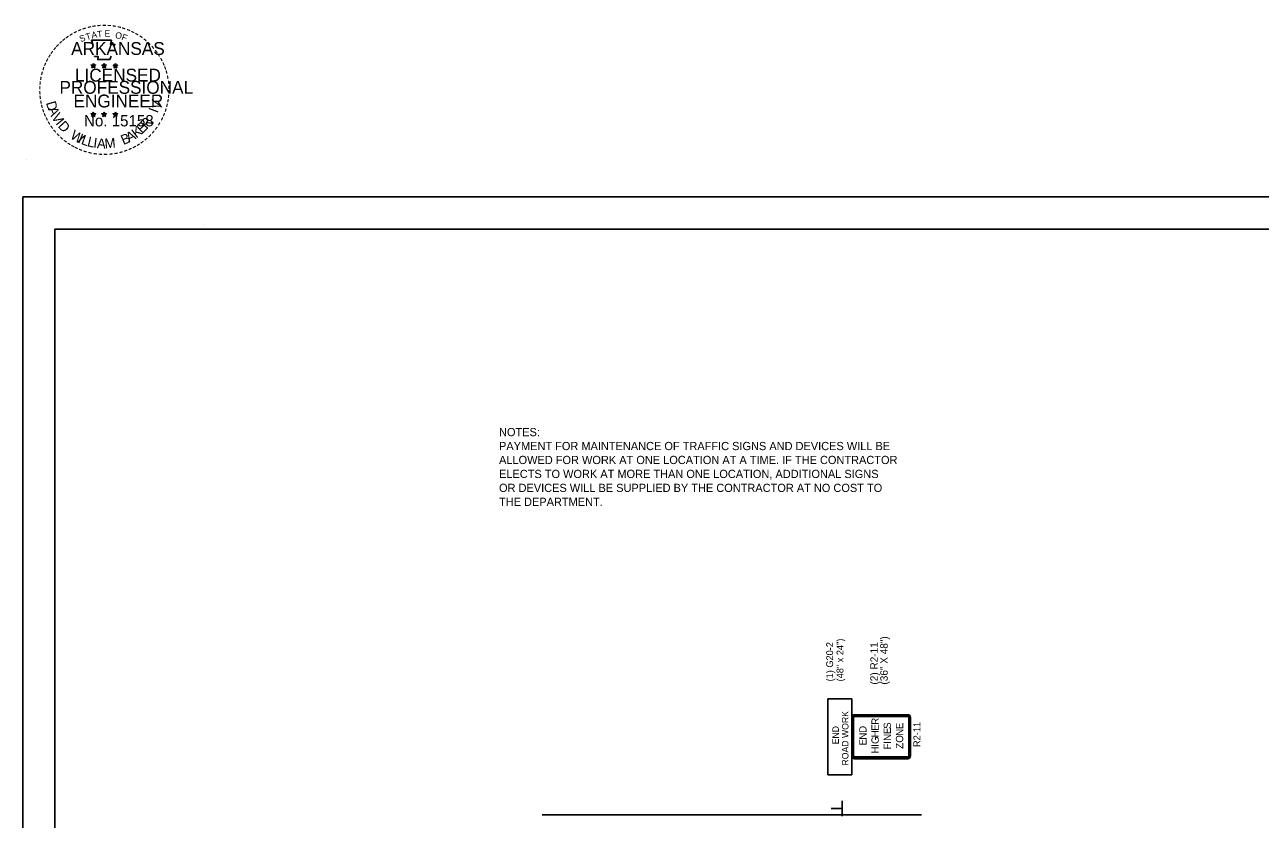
# Model space of a CAD drawing. Extents: x 32485 to 39285, y 55121 to 58033.
# Drawn here: x 35886 to 36848, y 57379 to 57998 of the extents above; entities that cross this region are included whole.
import ezdxf

# ---------------------------------------------------------------- set-up
doc = ezdxf.new("R2010")
doc.units = 0
for name, color, linetype in [('Default', 7, 'Continuous'), ('R_Border', 7, 'Continuous'), ('R_Border Notes', 7, 'Continuous'), ('R_Dimension', 7, 'Continuous'), ('R_Draft', 7, 'Continuous'), ('R_Exist Surface', 7, 'Continuous'), ('SHET_Stamp-PE-Chief-Eng', 7, 'Continuous')]:
    doc.layers.add(name, color=color, linetype=linetype)

msp = doc.modelspace()

# ---------------------------------------------------------------- linework, layer by layer
at = {"layer": 'Default'}
for p, q in [((36530.23, 57458.5), (36530.23, 57428.52)), ((36530.82, 57458.5), (36530.82, 57428.52)), ((36531.65, 57428.52), (36531.65, 57458.5)), ((36573.77, 57460.65), (36532.37, 57460.65)), ((36573.77, 57460.05), (36532.37, 57460.05)), ((36532.37, 57459.22), (36573.77, 57459.22)), ((36574.48, 57458.5), (36574.48, 57428.52)), ((36575.32, 57428.52), (36575.32, 57458.5)), ((36575.91, 57428.52), (36575.91, 57458.5)), ((36573.77, 57427.81), (36532.37, 57427.81)), ((36532.37, 57426.98), (36573.77, 57426.98)), ((36532.37, 57426.38), (36573.77, 57426.38))]:
    msp.add_line(p, q, dxfattribs=at)
msp.add_lwpolyline([(35885, 57863.91), (35885, 56763.91), (37585, 56763.91), (37585, 57863.91)], close=True, dxfattribs=at)
for centre, radius, start, end in [((36532.37, 57458.5), 2.14, 90, 180), ((36532.37, 57458.5), 1.55, 90, 180), ((36532.37, 57458.5), 0.714, 90, 180), ((36573.77, 57458.5), 2.14, 0.00001, 90.00001), ((36573.77, 57458.5), 1.55, 0, 90.00001), ((36573.77, 57458.5), 0.714, 0, 90.00001), ((36532.37, 57428.52), 2.14, 180, 270), ((36532.37, 57428.52), 1.55, 180, 270.00001), ((36532.37, 57428.52), 0.714, 180, 270.00001), ((36573.77, 57428.52), 2.14, 270, 0.00001), ((36573.77, 57428.52), 1.55, 270.00001, 0), ((36573.77, 57428.52), 0.714, 270.00001, 0)]:
    msp.add_arc(centre, radius, start, end, dxfattribs=at)
at = {"layer": 'R_Border'}
for p, q in [((36511.61, 57473.14), (36511.61, 57413.89)), ((36530.23, 57473.14), (36511.61, 57473.14)), ((36530.23, 57473.14), (36530.23, 57413.89)), ((36530.23, 57413.89), (36511.61, 57413.89)), ((36522.44, 57387.6), (36514.22, 57387.56)), ((36522.59, 57393.59), (36522.64, 57381.54))]:
    msp.add_line(p, q, dxfattribs=at)
at = {"layer": 'R_Border Notes'}
msp.add_line((36026.11, 57842.49), (36026.11, 57842.49), dxfattribs=at)
msp.add_line((36026.11, 57842.49), (36026.11, 57842.49), dxfattribs=at)
for points in [[(35885, 56763.91), (37585, 56763.91), (37585, 57863.91), (35885, 57863.91)], [(35910, 56788.91), (37560, 56788.91), (37560, 57838.91), (35910, 57838.91)]]:
    msp.add_lwpolyline(points, close=True, dxfattribs=at)
at = {"layer": 'R_Dimension'}
for p, q in [((35938.12, 57966.59), (35939.86, 57966.03)), ((35938.12, 57966.59), (35939.38, 57966.36)), ((35938.12, 57966.59), (35939.3, 57965.98)), ((35938.78, 57964.55), (35939.86, 57966.03)), ((35938.78, 57964.55), (35939.41, 57965.77)), ((35938.78, 57964.55), (35939.85, 57965.63)), ((35939.86, 57967.86), (35939.66, 57966.6)), ((35940.93, 57964.55), (35939.85, 57965.62)), ((35939.86, 57966.03), (35939.86, 57967.86)), ((35939.86, 57967.86), (35940.11, 57966.61)), ((35941.6, 57966.59), (35939.86, 57966.03)), ((35940.93, 57964.55), (35939.86, 57966.03)), ((35941.6, 57966.59), (35940.17, 57966.34)), ((35940.93, 57964.55), (35940.24, 57966)), ((35941.6, 57966.59), (35940.58, 57966.08)), ((35946.47, 57966.59), (35948.21, 57966.03)), ((35946.47, 57966.59), (35947.73, 57966.36)), ((35946.47, 57966.59), (35947.65, 57965.98)), ((35947.13, 57964.55), (35948.21, 57966.03)), ((35947.13, 57964.55), (35947.76, 57965.77)), ((35947.13, 57964.55), (35948.2, 57965.63)), ((35948.21, 57967.86), (35948.01, 57966.6)), ((35949.28, 57964.55), (35948.2, 57965.62)), ((35948.21, 57966.03), (35948.21, 57967.86)), ((35948.21, 57967.86), (35948.46, 57966.61)), ((35949.95, 57966.59), (35948.21, 57966.03)), ((35949.28, 57964.55), (35948.21, 57966.03)), ((35949.95, 57966.59), (35948.52, 57966.34)), ((35949.28, 57964.55), (35948.59, 57966)), ((35949.95, 57966.59), (35948.93, 57966.08)), ((35955.29, 57966.53), (35957.03, 57965.97)), ((35955.29, 57966.53), (35956.55, 57966.3)), ((35955.29, 57966.53), (35956.47, 57965.92)), ((35955.95, 57964.49), (35957.03, 57965.97)), ((35955.95, 57964.49), (35956.58, 57965.71)), ((35955.95, 57964.49), (35957.02, 57965.57)), ((35957.03, 57967.8), (35956.83, 57966.54)), ((35958.1, 57964.49), (35957.02, 57965.56)), ((35957.03, 57965.97), (35957.03, 57967.8)), ((35957.03, 57967.8), (35957.28, 57966.55)), ((35958.77, 57966.53), (35957.03, 57965.97)), ((35958.1, 57964.49), (35957.03, 57965.97)), ((35958.77, 57966.53), (35957.34, 57966.28)), ((35958.1, 57964.49), (35957.41, 57965.94)), ((35958.77, 57966.53), (35957.75, 57966.02)), ((35938.1, 57928.72), (35939.84, 57928.17)), ((35938.1, 57928.72), (35939.36, 57928.5)), ((35938.1, 57928.72), (35939.28, 57928.11)), ((35938.76, 57926.68), (35939.84, 57928.17)), ((35938.76, 57926.68), (35939.39, 57927.9)), ((35938.76, 57926.68), (35939.83, 57927.77)), ((35939.84, 57929.99), (35939.64, 57928.73)), ((35940.91, 57926.68), (35939.83, 57927.75)), ((35939.84, 57928.17), (35939.84, 57929.99)), ((35939.84, 57929.99), (35940.09, 57928.74)), ((35941.58, 57928.72), (35939.84, 57928.17)), ((35940.91, 57926.68), (35939.84, 57928.17)), ((35941.58, 57928.72), (35940.15, 57928.48)), ((35940.91, 57926.68), (35940.22, 57928.14)), ((35941.58, 57928.72), (35940.56, 57928.21)), ((35946.44, 57928.72), (35948.19, 57928.17)), ((35946.44, 57928.72), (35947.71, 57928.5)), ((35946.44, 57928.72), (35947.63, 57928.11)), ((35947.11, 57926.68), (35948.19, 57928.17)), ((35947.11, 57926.68), (35947.74, 57927.9)), ((35947.11, 57926.68), (35948.18, 57927.77)), ((35948.19, 57929.99), (35947.98, 57928.73)), ((35949.25, 57926.68), (35948.18, 57927.75)), ((35948.19, 57928.17), (35948.19, 57929.99)), ((35948.19, 57929.99), (35948.43, 57928.74)), ((35949.92, 57928.72), (35948.19, 57928.17)), ((35949.25, 57926.68), (35948.19, 57928.17)), ((35949.92, 57928.72), (35948.49, 57928.48)), ((35949.25, 57926.68), (35948.57, 57928.14)), ((35949.92, 57928.72), (35948.9, 57928.21)), ((35955.28, 57928.67), (35957.02, 57928.12)), ((35955.28, 57928.67), (35956.54, 57928.45)), ((35955.28, 57928.67), (35956.46, 57928.06)), ((35955.94, 57926.63), (35957.02, 57928.12)), ((35955.94, 57926.63), (35956.57, 57927.85)), ((35955.94, 57926.63), (35957.01, 57927.72)), ((35957.02, 57929.94), (35956.82, 57928.68)), ((35958.09, 57926.63), (35957.01, 57927.7)), ((35957.02, 57928.12), (35957.02, 57929.94)), ((35957.02, 57929.94), (35957.27, 57928.69)), ((35958.76, 57928.67), (35957.02, 57928.12)), ((35958.09, 57926.63), (35957.02, 57928.12)), ((35958.76, 57928.67), (35957.33, 57928.43)), ((35958.09, 57926.63), (35957.4, 57928.09)), ((35958.76, 57928.67), (35957.74, 57928.16))]:
    msp.add_line(p, q, dxfattribs=at)
for points in [[(35938.32, 57985.98), (35939.67, 57981.84)], [(35955.88, 57981.37), (35956.59, 57982.79), (35953.16, 57982.67), (35953.9, 57985.98), (35938.32, 57985.98)], [(35940.78, 57973.86), (35940.78, 57973.43), (35943.6, 57973.33), (35943.33, 57970.97), (35952.68, 57970.97), (35953.68, 57973.65)], [(35939.86, 57967.86), (35940.93, 57964.55), (35938.12, 57966.59), (35941.6, 57966.59), (35938.78, 57964.55), (35939.86, 57967.86)], [(35948.21, 57967.86), (35949.28, 57964.55), (35946.47, 57966.59), (35949.95, 57966.59), (35947.13, 57964.55), (35948.21, 57967.86)], [(35957.03, 57967.8), (35958.1, 57964.49), (35955.29, 57966.53), (35958.77, 57966.53), (35955.95, 57964.49), (35957.03, 57967.8)], [(35939.84, 57929.99), (35940.91, 57926.68), (35938.1, 57928.72), (35941.58, 57928.72), (35938.76, 57926.68), (35939.84, 57929.99)], [(35948.19, 57929.99), (35949.25, 57926.68), (35946.44, 57928.72), (35949.92, 57928.72), (35947.11, 57926.68), (35948.19, 57929.99)], [(35957.02, 57929.94), (35958.09, 57926.63), (35955.28, 57928.67), (35958.76, 57928.67), (35955.94, 57926.63), (35957.02, 57929.94)]]:
    msp.add_lwpolyline(points, dxfattribs=at)
for centre, radius in [((35939.86, 57966.03), 0.861), ((35939.86, 57966.03), 0.723), ((35939.86, 57966.03), 0.579), ((35939.86, 57966.03), 0.495), ((35939.86, 57966.03), 0.374), ((35939.86, 57966.03), 0.248), ((35939.86, 57966.03), 0.148), ((35948.21, 57966.03), 0.861), ((35948.21, 57966.03), 0.723), ((35948.21, 57966.03), 0.579), ((35948.21, 57966.03), 0.495), ((35948.21, 57966.03), 0.374), ((35948.21, 57966.03), 0.248), ((35948.21, 57966.03), 0.148), ((35957.03, 57965.97), 0.861), ((35957.03, 57965.97), 0.723), ((35957.03, 57965.97), 0.579), ((35957.03, 57965.97), 0.495), ((35957.03, 57965.97), 0.374), ((35957.03, 57965.97), 0.248), ((35957.03, 57965.97), 0.148), ((35939.84, 57928.16), 0.861), ((35939.84, 57928.16), 0.723), ((35939.84, 57928.16), 0.579), ((35939.84, 57928.16), 0.495), ((35939.84, 57928.16), 0.374), ((35939.84, 57928.16), 0.248), ((35939.84, 57928.16), 0.148), ((35948.18, 57928.16), 0.861), ((35948.18, 57928.16), 0.723), ((35948.18, 57928.16), 0.579), ((35948.18, 57928.16), 0.495), ((35948.18, 57928.16), 0.374), ((35948.18, 57928.16), 0.248), ((35948.18, 57928.16), 0.148), ((35957.02, 57928.11), 0.861), ((35957.02, 57928.11), 0.723), ((35957.02, 57928.11), 0.579), ((35957.02, 57928.11), 0.495), ((35957.02, 57928.11), 0.374), ((35957.02, 57928.11), 0.248), ((35957.02, 57928.11), 0.148)]:
    msp.add_circle(centre, radius, dxfattribs=at)
at = {"layer": 'R_Exist Surface'}
msp.add_line((36289.08, 57382.7), (36584.44, 57382.7), dxfattribs=at)
at = {"layer": 'SHET_Stamp-PE-Chief-Eng'}
msp.add_line((35887.86, 57893.03), (35887.86, 57893.03), dxfattribs=at)

# ---------------------------------------------------------------- texts
at = {"layer": 'Default'}
for s, height, p in [('NOTES: ', 6.392, (36255.62, 57677.6)), ('PAYMENT FOR MAINTENANCE OF TRAFFIC SIGNS AND DEVICES WILL BE ', 6.3923, (36255.62, 57666.73)), ('ALLOWED FOR WORK AT ONE LOCATION AT A TIME. IF THE CONTRACTOR', 6.3923, (36255.62, 57655.87)), ('ELECTS TO WORK AT MORE THAN ONE LOCATION, ADDITIONAL SIGNS', 6.3923, (36255.62, 57645)), ('OR DEVICES WILL BE SUPPLIED BY THE CONTRACTOR AT NO COST TO ', 6.3923, (36255.62, 57634.13)), ('THE DEPARTMENT.', 6.3923, (36255.62, 57623.27))]:
    msp.add_text(s, height=height, dxfattribs=at).set_placement(p)
for s, height, p in [('R', 5.71, (36551.17, 57452.75)), ('E', 5.71, (36551.17, 57448.23)), ('S', 5.71, (36560.68, 57449.6)), ('E', 5.71, (36570.2, 57449.4)), ('R2-11', 5.384, (36583.53, 57435.46)), ('D', 5.71, (36541.65, 57446.46)), ('N', 5.71, (36541.65, 57441.2)), ('G', 5.71, (36551.17, 57437.83)), ('H', 5.71, (36551.17, 57442.97)), ('E', 5.71, (36560.68, 57445.49)), ('N', 5.71, (36560.68, 57440.23)), ('O', 5.71, (36570.2, 57438.83)), ('N', 5.71, (36570.2, 57444.14)), ('E', 5.71, (36541.65, 57436.68)), ('I', 5.71, (36551.17, 57435.66)), ('H', 5.71, (36551.17, 57430.4)), ('I', 5.71, (36560.68, 57437.94)), ('F', 5.71, (36560.68, 57433.54)), ('Z', 5.71, (36570.2, 57434.08))]:
    msp.add_text(s, height=height, rotation=90, dxfattribs=at).set_placement(p)
at = {"layer": 'R_Border'}
for s, height, p in [('(1) G20-2', 5.353, (36515.65, 57486.59)), ('(48" x 24")', 5.3523, (36523.68, 57486.59)), ('ROAD WORK', 5.058, (36527.6, 57421.06)), ('END', 5.058, (36520.13, 57437.57))]:
    msp.add_text(s, height=height, rotation=90, dxfattribs=at).set_placement(p)
at = {"layer": 'R_Dimension'}
for s, height, rotation, p in [('-', 8, 34.06357, (35922.74, 57986.83)), ('-', 8, 28.79182, (35925.73, 57988.68)), ('-', 8, 24.30721, (35928.89, 57990.27)), ('-', 8, 19.17608, (35932.06, 57991.61)), ('T', 5, 16.4036, (35934.67, 57986.02)), ('-', 8, 13.63015, (35935.81, 57992.82)), ('A', 5, 11.21318, (35938.8, 57987.28)), ('-', 8, 10.21935, (35939.2, 57993.63)), ('T', 5, 6.02276, (35943.04, 57988.11)), ('-', 8, 5.89682, (35942.85, 57994.18)), ('-', 8, 0.18623, (35946.71, 57994.54)), ('E', 5, 0.83234, (35948.57, 57988.66)), ('-', 8, 357.74304, (35950.32, 57994.47)), ('-', 8, 352.16172, (35954.04, 57994.19)), ('O', 5, 350.4515, (35956.59, 57987.61)), ('-', 8, 347.20489, (35957.64, 57993.62)), ('-', 8, 342.3362, (35960.81, 57992.85)), ('-', 8, 337.85509, (35964.49, 57991.73)), ('-', 8, 334.12109, (35967.64, 57990.38)), ('-', 8, 329.64089, (35970.54, 57988.96)), ('-', 8, 48.42305, (35913.07, 57978.49)), ('-', 8, 42.96224, (35915.31, 57980.88)), ('-', 8, 38.95066, (35917.47, 57982.97)), ('-', 8, 36.23174, (35919.85, 57984.86)), ('S', 5, 21.59401, (35930.1, 57984.37)), ('F', 5, 340.07066, (35961.36, 57986.47)), ('-', 8, 325.86266, (35973.75, 57987.16)), ('-', 8, 320.52971, (35976.8, 57985.03)), ('-', 8, 315.57859, (35979.8, 57982.59)), ('-', 8, 309.87973, (35982.64, 57979.84)), ('-', 8, 58.07063, (35907.36, 57970.59)), ('-', 8, 54.23247, (35908.99, 57973.23)), ('-', 8, 50.61418, (35911.05, 57976.06)), ('-', 8, 306.65218, (35985.27, 57976.83)), ('-', 7, 303.67529, (35987.7, 57973.99)), ('-', 8, 299.66835, (35989.29, 57970.95)), ('-', 8, 72.39447, (35903.41, 57961.32)), ('-', 8, 67.77427, (35904.5, 57964.47)), ('-', 8, 62.87135, (35905.8, 57967.52)), ('-', 8, 294.66279, (35990.91, 57967.89)), ('-', 8, 290.57283, (35992.2, 57965.01)), ('-', 8, 285.12326, (35993.37, 57962.11)), ('-', 8, 85.18634, (35901.38, 57950.73)), ('-', 8, 81.20126, (35901.76, 57954.18)), ('-', 8, 75.46096, (35902.42, 57957.75)), ('-', 8, 280.54934, (35994.37, 57958.4)), ('-', 8, 276.59616, (35995.18, 57954.56)), ('-', 8, 94.19588, (35901.43, 57943.6)), ('-', 8, 89.06224, (35901.26, 57947.22)), ('-', 8, 263.5172, (35995.55, 57944.46)), ('-', 8, 274.33011, (35995.48, 57950.95)), ('-', 8, 269.94067, (35995.65, 57947.79)), ('-', 8, 98.94793, (35901.79, 57940.26)), ('-', 8, 101.71495, (35902.47, 57936.6)), ('-', 8, 105.45785, (35903.28, 57933.62)), ('D', 7.7, 286.28478, (35902.91, 57937.29)), ('V', 7.7, 72.65729, (35990.87, 57931.48)), ('-', 8, 255.7626, (35994.65, 57937.8)), ('-', 8, 260.99529, (35995.2, 57941.19)), ('-', 8, 109.08742, (35904.35, 57930.47)), ('-', 8, 114.06432, (35905.62, 57927.49)), ('-', 8, 115.72885, (35907.15, 57924.4)), ('A', 7.7, 292.78351, (35904.37, 57932.28)), ('V', 7.7, 300.79357, (35906.94, 57926.38)), ('I', 7.7, 308.35023, (35910.1, 57921.2)), ('R', 7.7, 50.36514, (35981.51, 57916.34)), ('I', 7.7, 69.03009, (35989.76, 57928.79)), ('-', 8, 244.61971, (35991.32, 57927.69)), ('-', 8, 247.88866, (35992.63, 57930.83)), ('-', 8, 252.86809, (35993.74, 57934.2)), ('-', 8, 120.44712, (35908.93, 57921.47)), ('-', 8, 125.89344, (35910.95, 57918.66)), ('-', 8, 130.71812, (35913.26, 57915.9)), ('D', 7.7, 311.97742, (35911.85, 57918.87)), ('W', 7.7, 328.07311, (35921.24, 57910.04)), ('A', 7.7, 28.90423, (35967.7, 57906.17)), ('K', 7.7, 36.91429, (35973.29, 57909.35)), ('E', 7.7, 44.01755, (35977.84, 57912.8)), (',', 7.7, 57.4684, (35985.12, 57920.76)), ('-', 8, 231.25377, (35985.19, 57917.83)), ('-', 8, 233.84524, (35987.34, 57920.66)), ('-', 8, 239.07125, (35989.35, 57923.93)), ('-', 8, 134.22381, (35915.84, 57913.18)), ('-', 8, 138.93382, (35918.47, 57910.86)), ('-', 8, 144.64634, (35921.25, 57908.83)), ('-', 8, 148.08978, (35924.05, 57906.97)), ('I', 7.7, 336.6877, (35927.18, 57906.49)), ('L', 7.7, 340.3149, (35929.83, 57905.27)), ('L', 7.7, 346.66249, (35934.63, 57903.55)), ('I', 7.7, 353.01009, (35939.58, 57902.36)), ('A', 7.7, 356.63729, (35942.47, 57901.94)), ('M', 7.7, 4.64735, (35948.89, 57901.64)), ('B', 7.7, 22.8589, (35963.22, 57904.3)), ('-', 8, 212.24909, (35974.77, 57908.17)), ('-', 8, 215.73633, (35977.44, 57910.11)), ('-', 8, 221.08509, (35980.18, 57912.47)), ('-', 8, 225.76533, (35982.79, 57915.01)), ('-', 8, 151.57039, (35926.95, 57905.35)), ('-', 8, 154.60019, (35929.56, 57904.11)), ('-', 8, 158.56121, (35932.68, 57902.84)), ('-', 8, 162.79826, (35936.11, 57901.78)), ('-', 8, 167.55551, (35939.69, 57900.96)), ('-', 8, 173.11546, (35943.55, 57900.41)), ('-', 8, 176.51827, (35947.29, 57900.14)), ('-', 8, 181.59176, (35951.01, 57900.24)), ('-', 8, 185.81666, (35955.05, 57900.62)), ('-', 8, 191.28576, (35958.73, 57901.28)), ('-', 8, 195.47429, (35962.38, 57902.27)), ('-', 8, 199.46435, (35965.7, 57903.46)), ('-', 8, 204.25161, (35968.86, 57904.85)), ('-', 8, 207.35684, (35971.98, 57906.44))]:
    msp.add_text(s, height=height, rotation=rotation, dxfattribs=at).set_placement(p)
for s, height, p in [('ARKANSAS', 10, (35922.59, 57974.54)), ('LICENSED', 10, (35925.57, 57953.79)), ('PROFESSIONAL', 10, (35913.46, 57944.27)), ('ENGINEER', 10, (35924.39, 57933.65)), ('No. 15158', 8.785, (35932.6, 57918.89)), ('AAMU', 0.0001, (35947.85, 57901.62))]:
    msp.add_text(s, height=height, dxfattribs=at).set_placement(p)
at = {"layer": 'R_Draft'}
for s, height, p in [('(36" X 48")', 5.8301, (36558.17, 57484.13)), ('(2) R2-11', 5.83, (36550.45, 57484.13))]:
    msp.add_text(s, height=height, rotation=90, dxfattribs=at).set_placement(p)

doc.saveas('drawing.dxf')
